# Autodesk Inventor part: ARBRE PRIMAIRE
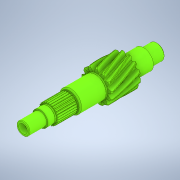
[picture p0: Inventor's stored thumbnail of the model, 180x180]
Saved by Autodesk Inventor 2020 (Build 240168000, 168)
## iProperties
Created: 2003-05
Part Number: ARBRE PRIMAIRE
Material: Générique
Document SubType Name: Modeling
Designer: Bruno
Density: 1 g/cm^3
Appearance: Par défaut
Author: Bruno
Sending System: SolidWorks 2011
Last Author: Professeur
Last Saved: 2014-11-10
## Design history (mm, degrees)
feature "Répétition circulaire2"
node "Solide1"
